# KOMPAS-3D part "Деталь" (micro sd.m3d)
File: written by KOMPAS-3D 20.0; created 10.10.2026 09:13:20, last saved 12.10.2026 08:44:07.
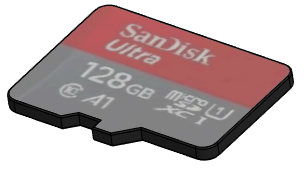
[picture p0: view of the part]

Document properties: Полное имя файла: D:\RicWork\Project-EPS32\box_compas\SD card\micro sd.m3d

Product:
- Part/product: Деталь
    Масса: 0.00121292

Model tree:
1. Эскиз:1
2. Элемент выдавливания:1
     Расстояние 1 = 1
3. Эскиз:2  (with: Элемент выдавливания:1)
4. Элемент выдавливания:2
     Расстояние 2 = 1
5. Фаска:1  (with: Элемент выдавливания:2)
     Угол = 45; Длина 1 = 1.6; Длина 2 = 1.6
6. Фаска:2  (with: Элемент выдавливания:2)
     Угол = 45; Длина 1 = 0.8; Длина 2 = 0.8
7. Скругление:1  (with: Элемент выдавливания:2, Элемент выдавливания:1)
     Радиус = 1
8. Скругление:2  (with: Элемент выдавливания:1)
     Радиус = 0.1

Referenced files in D:\myProjects\Progect_esp32\box_compas\: micro sd.png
